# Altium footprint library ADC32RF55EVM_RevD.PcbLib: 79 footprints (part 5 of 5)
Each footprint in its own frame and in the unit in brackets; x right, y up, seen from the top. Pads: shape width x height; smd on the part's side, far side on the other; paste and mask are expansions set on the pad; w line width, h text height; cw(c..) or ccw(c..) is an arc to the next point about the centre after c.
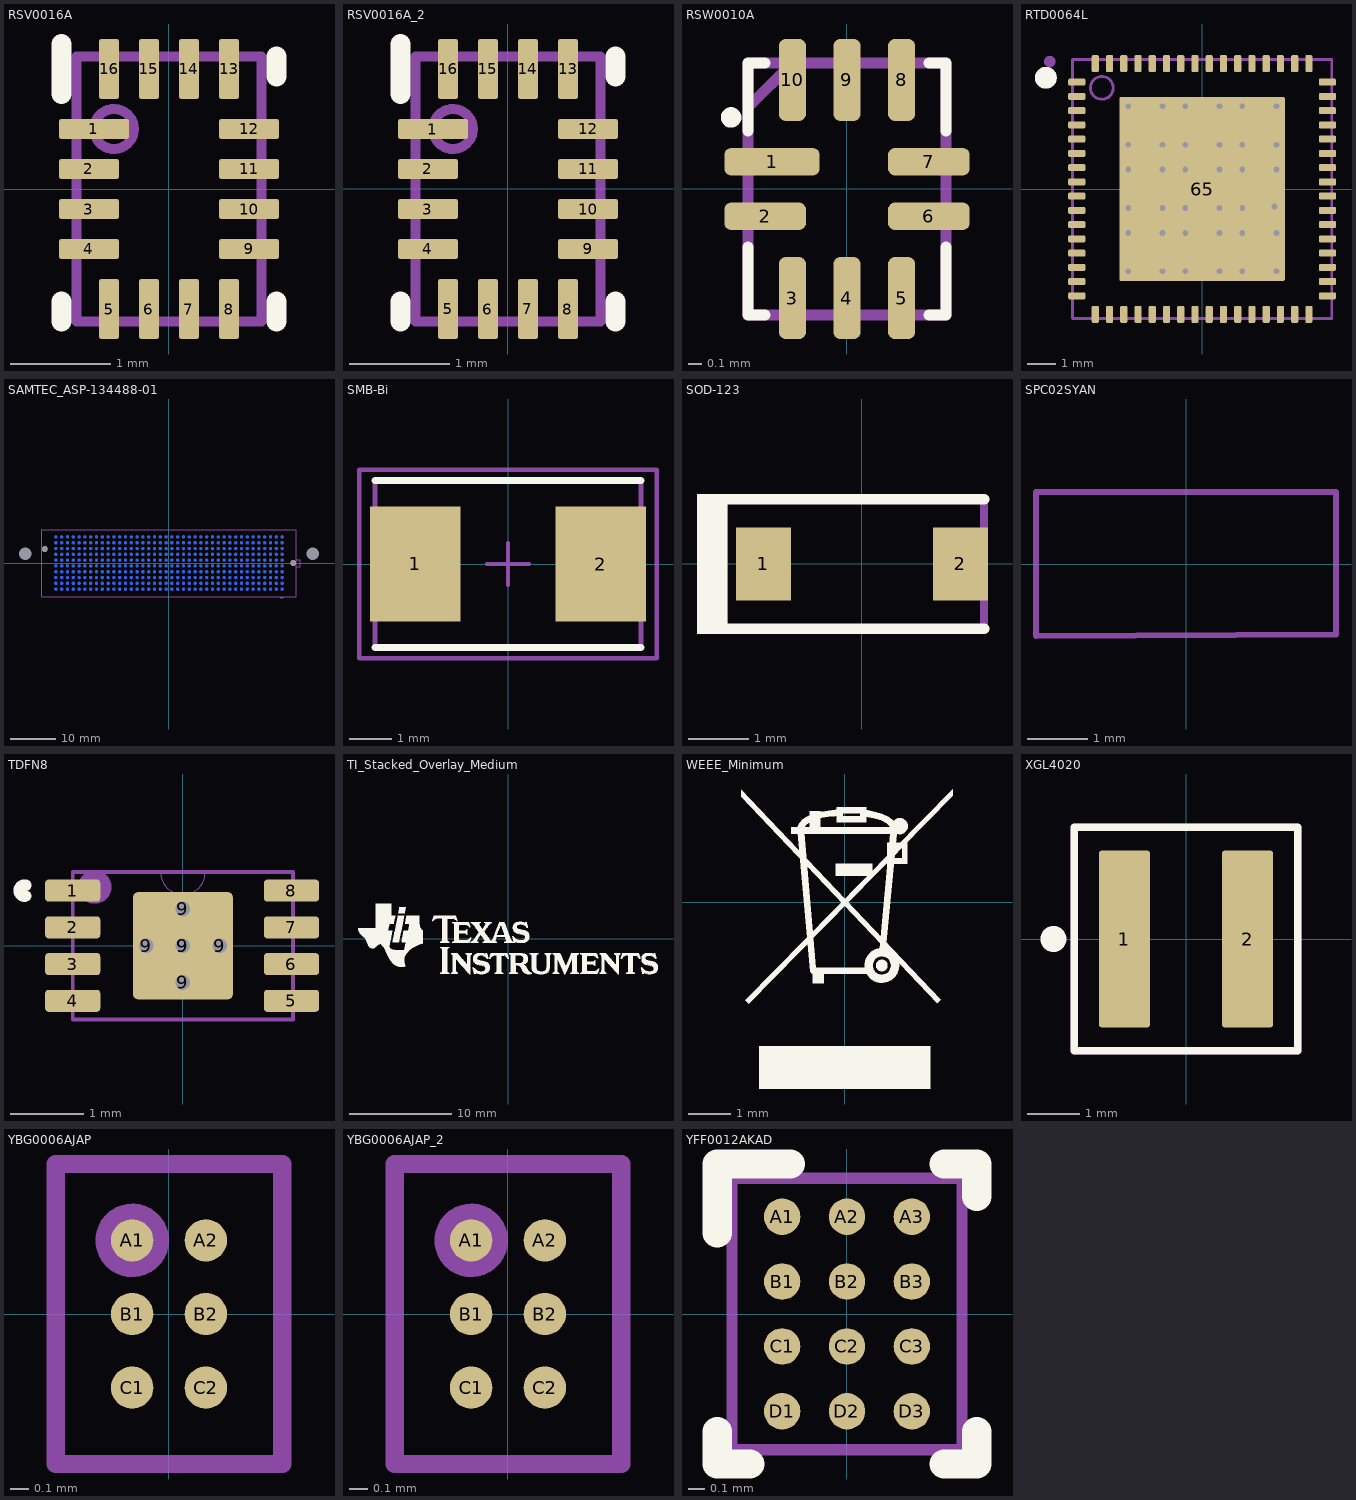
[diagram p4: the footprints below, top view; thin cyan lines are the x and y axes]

## RSV0016A [mm] "QFN, 16-Leads, Body 1.8x2.6mm, Pitch 0.4mm, TI Recommended"
height 0.55
pads (16):
  rrect25% 0.7x0.2 smd mask+0.05: 1(-0.75,0.6)
  rrect25% 0.6x0.2 smd mask+0.05: 2(-0.8,0.2) 3(-0.8,-0.2) 4(-0.8,-0.6) 9(0.8,-0.6) 10(0.8,-0.2) 11(0.8,0.2) 12(0.8,0.6)
  rrect25% 0.2x0.6 smd mask+0.05: 5(-0.6,-1.2) 6(-0.2,-1.2) 7(0.2,-1.2) 8(0.6,-1.2) 13(0.6,1.2) 14(0.2,1.2) 15(-0.2,1.2) 16(-0.6,1.2)
Top Overlay:
  lines w0.2: -1.075,-1.325 -1.075,-1.125 ; -1.075,0.95 -1.075,1.45 ; 1.075,-1.325 1.075,-1.125 ; 1.075,1.125 1.075,1.325
Mechanical 5:
  circle w0.1: c-0.55,0.6 r0.2
  lines w0.1: -0.925,-1.325 -0.925,1.325 0.925,1.325 0.925,-1.325 -0.925,-1.325
  text ".Designator" at -0.254,0 h0.64
3D body "RSV0016A.step": height 0.49, standoff 0, extent -0.855,-1.305 0.855,1.305

## RSV0016A_2 [mm]
pads (16):
  rrect25% 0.7x0.2 smd mask+0.05: 1(-0.75,0.6)
  rrect25% 0.6x0.2 smd mask+0.05: 2(-0.8,0.2) 3(-0.8,-0.2) 4(-0.8,-0.6) 9(0.8,-0.6) 10(0.8,-0.2) 11(0.8,0.2) 12(0.8,0.6)
  rrect25% 0.2x0.6 smd mask+0.05: 5(-0.6,-1.2) 6(-0.2,-1.2) 7(0.2,-1.2) 8(0.6,-1.2) 13(0.6,1.2) 14(0.2,1.2) 15(-0.2,1.2) 16(-0.6,1.2)
Top Overlay:
  lines w0.2: -1.075,-1.325 -1.075,-1.125 ; -1.075,0.95 -1.075,1.45 ; 1.075,-1.325 1.075,-1.125 ; 1.075,1.125 1.075,1.325
Mechanical 5:
  circle w0.1: c-0.55,0.6 r0.2
  lines w0.1: -0.925,-1.325 -0.925,1.325 0.925,1.325 0.925,-1.325 -0.925,-1.325
  text ".Designator" at -0.254,0 h0.64
3D body: height 0.56, standoff 0.4, extent -0.749,0.401 -0.351,0.799
3D body: height 0.55, standoff 0, extent -0.925,-1.325 0.925,1.325

## RSW0010A [mm]
height 4.27
pads (10):
  rrect50% 0.7x0.2 smd mask+0.05: 1(-0.55,0.2)
  rrect50% 0.6x0.2 smd mask+0.05: 2(-0.6,-0.2) 6(0.6,-0.2) 7(0.6,0.2)
  rrect50% 0.2x0.6 smd mask+0.05: 3(-0.4,-0.8) 4(0,-0.8) 5(0.4,-0.8) 8(0.4,0.8) 9(0,0.8) 10(-0.4,0.8)
Top Overlay:
  circle w0.1: c-0.85,0.525 r0.025
  lines w0.08: -0.725,-0.425 -0.725,-0.925 -0.6,-0.925 ; -0.725,0.425 -0.725,0.925 -0.6,0.925 ; 0.6,-0.925 0.725,-0.925 0.725,-0.425 ; 0.6,0.925 0.725,0.925 0.725,0.425
Mechanical 5:
  lines w0.08: -0.725,0.525 -0.725,0.55 -0.725,0.6 -0.4,0.925 ; -0.725,-0.925 -0.725,0.925 ; -0.725,-0.925 -0.725,0.925 ; -0.725,-0.925 0.725,-0.925 ; -0.725,-0.925 0.725,-0.925 ; -0.725,0.925 0.725,0.925 ; -0.725,0.925 0.725,0.925 ; 0.725,-0.925 0.725,0.925 ; 0.725,-0.925 0.725,0.925
  text ".Designator" at -0.254,0 h0.64
3D body "RSW0010A.stp": height 0.55, standoff 0, extent -0.7,-0.9 0.7,0.9

## RTD0064L [mm] "VQFN-64"
height 0.9
pads (65):
  rrect40% 0.6x0.25 smd: 1(-4.4,3.75) 2(-4.4,3.25) 3(-4.4,2.75) 4(-4.4,2.25) 5(-4.4,1.75) 6(-4.4,1.25) 7(-4.4,0.75) 8(-4.4,0.25) 9(-4.4,-0.25) 10(-4.4,-0.75) 11(-4.4,-1.25) 12(-4.4,-1.75) 13(-4.4,-2.25) 14(-4.4,-2.75) 15(-4.4,-3.25) 16(-4.4,-3.75) 33(4.4,-3.75) 34(4.4,-3.25) 35(4.4,-2.75) 36(4.4,-2.25) 37(4.4,-1.75) 38(4.4,-1.25) 39(4.4,-0.75) 40(4.4,-0.25) 41(4.4,0.25) 42(4.4,0.75) 43(4.4,1.25) 44(4.4,1.75) 45(4.4,2.25) 46(4.4,2.75) 47(4.4,3.25) 48(4.4,3.75)
  rrect40% 0.25x0.6 smd: 17(-3.75,-4.4) 18(-3.25,-4.4) 19(-2.75,-4.4) 20(-2.25,-4.4) 21(-1.75,-4.4) 22(-1.25,-4.4) 23(-0.75,-4.4) 24(-0.25,-4.4) 25(0.25,-4.4) 26(0.75,-4.4) 27(1.25,-4.4) 28(1.75,-4.4) 29(2.25,-4.4) 30(2.75,-4.4) 31(3.25,-4.4) 32(3.75,-4.4) 49(3.75,4.4) 50(3.25,4.4) 51(2.75,4.4) 52(2.25,4.4) 53(1.75,4.4) 54(1.25,4.4) 55(0.75,4.4) 56(0.25,4.4) 57(-0.25,4.4) 58(-0.75,4.4) 59(-1.25,4.4) 60(-1.75,4.4) 61(-2.25,4.4) 62(-2.75,4.4) 63(-3.25,4.4) 64(-3.75,4.4)
  rrect2% 5.808x6.466 smd paste-3.5: 65(0,0)
via 0.609,-2.889 diameter 0.457 hole 0.203
via -1.393,-2.889 diameter 0.457 hole 0.203
via 0.609,-0.667 diameter 0.457 hole 0.203
via -2.595,-1.541 diameter 0.457 hole 0.203
via -2.595,-2.889 diameter 0.457 hole 0.203
via -1.393,-1.541 diameter 0.457 hole 0.203
via -0.593,-1.541 diameter 0.457 hole 0.203
via 0.609,-1.541 diameter 0.457 hole 0.203
via 1.41,-1.541 diameter 0.457 hole 0.203
via 1.41,-2.889 diameter 0.457 hole 0.203
via 2.612,-2.889 diameter 0.457 hole 0.203
via 2.612,-1.541 diameter 0.457 hole 0.203
via -0.593,-2.889 diameter 0.457 hole 0.203
via 0.609,0.681 diameter 0.457 hole 0.203
via -2.595,0.681 diameter 0.457 hole 0.203
via -0.593,-0.667 diameter 0.457 hole 0.203
via -1.393,-0.667 diameter 0.457 hole 0.203
via -2.595,-0.667 diameter 0.457 hole 0.203
via -0.593,0.681 diameter 0.457 hole 0.203
via -1.393,0.681 diameter 0.457 hole 0.203
via 1.41,-0.667 diameter 0.457 hole 0.203
via 1.41,1.555 diameter 0.457 hole 0.203
via 1.41,0.681 diameter 0.457 hole 0.203
via 2.612,1.555 diameter 0.457 hole 0.203
via 2.612,0.681 diameter 0.457 hole 0.203
via 2.54,-0.61 diameter 0.457 hole 0.203
via -2.595,2.903 diameter 0.457 hole 0.203
via -1.393,2.903 diameter 0.457 hole 0.203
via 2.612,2.903 diameter 0.457 hole 0.203
via 0.609,1.555 diameter 0.457 hole 0.203
via 0.609,2.903 diameter 0.457 hole 0.203
via -0.593,1.555 diameter 0.457 hole 0.203
via -0.593,2.903 diameter 0.457 hole 0.203
via -1.393,1.555 diameter 0.457 hole 0.203
via -2.595,1.555 diameter 0.457 hole 0.203
via 1.41,2.903 diameter 0.457 hole 0.203
Top Overlay:
  circle w0.2: c-5.482,3.903 r0.284
  region: -5.831,3.903 -5.502,4.231 -5.127,3.857 -5.456,3.528
Top Paste:
  drawing of 9 lines, arcs and shapes, not listed
Mechanical 5:
  circle w0.1: c-3.52,3.55 r0.4
  lines w0.1: -3.145,4.55 -2.895,4.55 -2.645,4.55 ; -4.55,-4.55 4.55,-4.55 4.55,4.55 -4.55,4.55 -4.55,-4.55
  text ".Designator" at 0,0 h0.51
Mechanical 13:
  circle w0.2: c-5.346,4.473 r0.1
3D body: height 0.9, standoff 0, extent -3.919,3.151 -3.121,3.949
3D body "RTD0064L.stp": height 0.85, standoff 0, extent -4.5,-4.5 4.5,4.5

## SAMTEC_ASP-134488-01 [mm]
pads (404):
  round 0.64 smd far side paste+0.125: A1(24.79,-5.715) A2(23.52,-5.715) A3(22.25,-5.715) A4(20.98,-5.715) A5(19.71,-5.715) A6(18.44,-5.715) A7(17.17,-5.715) A8(15.9,-5.715) A9(14.63,-5.715) A10(13.36,-5.715) A11(12.09,-5.715) A12(10.82,-5.715) A13(9.55,-5.715) A14(8.28,-5.715) A15(7.01,-5.715) A16(5.74,-5.715) A17(4.47,-5.715) A18(3.2,-5.715) A19(1.93,-5.715) A20(0.66,-5.715) A21(-0.61,-5.715) A22(-1.88,-5.715) A23(-3.15,-5.715) A24(-4.42,-5.715) A25(-5.69,-5.715) A26(-6.96,-5.715) A27(-8.23,-5.715) A28(-9.5,-5.715) A29(-10.77,-5.715) A30(-12.04,-5.715) A31(-13.31,-5.715) A32(-14.58,-5.715) A33(-15.85,-5.715) A34(-17.12,-5.715) A35(-18.39,-5.715) A36(-19.66,-5.715) A37(-20.93,-5.715) A38(-22.2,-5.715) A39(-23.47,-5.715) A40(-24.74,-5.715) B1(24.79,-4.445) B2(23.52,-4.445) B3(22.25,-4.445) B4(20.98,-4.445) B5(19.71,-4.445) B6(18.44,-4.445) B7(17.17,-4.445) B8(15.9,-4.445) B9(14.63,-4.445) B10(13.36,-4.445) B11(12.09,-4.445) B12(10.82,-4.445) B13(9.55,-4.445) B14(8.28,-4.445) B15(7.01,-4.445) B16(5.74,-4.445) B17(4.47,-4.445) B18(3.2,-4.445) B19(1.93,-4.445) B20(0.66,-4.445) B21(-0.61,-4.445) B22(-1.88,-4.445) B23(-3.15,-4.445) B24(-4.42,-4.445) B25(-5.69,-4.445) B26(-6.96,-4.445) B27(-8.23,-4.445) B28(-9.5,-4.445) B29(-10.77,-4.445) B30(-12.04,-4.445) B31(-13.31,-4.445) B32(-14.58,-4.445) B33(-15.85,-4.445) B34(-17.12,-4.445) B35(-18.39,-4.445) B36(-19.66,-4.445) B37(-20.93,-4.445) B38(-22.2,-4.445) B39(-23.47,-4.445) B40(-24.74,-4.445) C1(24.79,-3.175) C2(23.52,-3.175) C3(22.25,-3.175) C4(20.98,-3.175) C5(19.71,-3.175) C6(18.44,-3.175) C7(17.17,-3.175) C8(15.9,-3.175) C9(14.63,-3.175) C10(13.36,-3.175) C11(12.09,-3.175) C12(10.82,-3.175) C13(9.55,-3.175) C14(8.28,-3.175) C15(7.01,-3.175) C16(5.74,-3.175) C17(4.47,-3.175) C18(3.2,-3.175) C19(1.93,-3.175) C20(0.66,-3.175) C21(-0.61,-3.175) C22(-1.88,-3.175) C23(-3.15,-3.175) C24(-4.42,-3.175) C25(-5.69,-3.175) C26(-6.96,-3.175) C27(-8.23,-3.175) C28(-9.5,-3.175) C29(-10.77,-3.175) C30(-12.04,-3.175) C31(-13.31,-3.175) C32(-14.58,-3.175) C33(-15.85,-3.175) C34(-17.12,-3.175) C35(-18.39,-3.175) C36(-19.66,-3.175) C37(-20.93,-3.175) C38(-22.2,-3.175) C39(-23.47,-3.175) C40(-24.74,-3.175) D1(24.79,-1.905) D2(23.52,-1.905) D3(22.25,-1.905) D4(20.98,-1.905) D5(19.71,-1.905) D6(18.44,-1.905) D7(17.17,-1.905) D8(15.9,-1.905) D9(14.63,-1.905) D10(13.36,-1.905) D11(12.09,-1.905) D12(10.82,-1.905) D13(9.55,-1.905) D14(8.28,-1.905) D15(7.01,-1.905) D16(5.74,-1.905) D17(4.47,-1.905) D18(3.2,-1.905) D19(1.93,-1.905) D20(0.66,-1.905) D21(-0.61,-1.905) D22(-1.88,-1.905) D23(-3.15,-1.905) D24(-4.42,-1.905) D25(-5.69,-1.905) D26(-6.96,-1.905) D27(-8.23,-1.905) D28(-9.5,-1.905) D29(-10.77,-1.905) D30(-12.04,-1.905) D31(-13.31,-1.905) D32(-14.58,-1.905) D33(-15.85,-1.905) D34(-17.12,-1.905) D35(-18.39,-1.905) D36(-19.66,-1.905) D37(-20.93,-1.905) D38(-22.2,-1.905) D39(-23.47,-1.905) D40(-24.74,-1.905) E1(24.79,-0.635) E2(23.52,-0.635) E3(22.25,-0.635) E4(20.98,-0.635) E5(19.71,-0.635) E6(18.44,-0.635) E7(17.17,-0.635) E8(15.9,-0.635) E9(14.63,-0.635) E10(13.36,-0.635) E11(12.09,-0.635) E12(10.82,-0.635) E13(9.55,-0.635) E14(8.28,-0.635) E15(7.01,-0.635) E16(5.74,-0.635) E17(4.47,-0.635) E18(3.2,-0.635) E19(1.93,-0.635) E20(0.66,-0.635) E21(-0.61,-0.635) E22(-1.88,-0.635) E23(-3.15,-0.635) E24(-4.42,-0.635) E25(-5.69,-0.635) E26(-6.96,-0.635) E27(-8.23,-0.635) E28(-9.5,-0.635) E29(-10.77,-0.635) E30(-12.04,-0.635) E31(-13.31,-0.635) E32(-14.58,-0.635) E33(-15.85,-0.635) E34(-17.12,-0.635) E35(-18.39,-0.635) E36(-19.66,-0.635) E37(-20.93,-0.635) E38(-22.2,-0.635) E39(-23.47,-0.635) E40(-24.74,-0.635) F1(24.79,0.635) F2(23.52,0.635) F3(22.25,0.635) F4(20.98,0.635) F5(19.71,0.635) F6(18.44,0.635) F7(17.17,0.635) F8(15.9,0.635) F9(14.63,0.635) F10(13.36,0.635) F11(12.09,0.635) F12(10.82,0.635) F13(9.55,0.635) F14(8.28,0.635) F15(7.01,0.635) F16(5.74,0.635) F17(4.47,0.635) F18(3.2,0.635) F19(1.93,0.635) F20(0.66,0.635) F21(-0.61,0.635) F22(-1.88,0.635) F23(-3.15,0.635) F24(-4.42,0.635) F25(-5.69,0.635) F26(-6.96,0.635) F27(-8.23,0.635) F28(-9.5,0.635) F29(-10.77,0.635) F30(-12.04,0.635) F31(-13.31,0.635) F32(-14.58,0.635) F33(-15.85,0.635) F34(-17.12,0.635) F35(-18.39,0.635) F36(-19.66,0.635) F37(-20.93,0.635) F38(-22.2,0.635) F39(-23.47,0.635) F40(-24.74,0.635) G1(24.79,1.905) G2(23.52,1.905) G3(22.25,1.905) G4(20.98,1.905) G5(19.71,1.905) G6(18.44,1.905) G7(17.17,1.905) G8(15.9,1.905) G9(14.63,1.905) G10(13.36,1.905) G11(12.09,1.905) G12(10.82,1.905) G13(9.55,1.905) G14(8.28,1.905) G15(7.01,1.905) G16(5.74,1.905) G17(4.47,1.905) G18(3.2,1.905) G19(1.93,1.905) G20(0.66,1.905) G21(-0.61,1.905) G22(-1.88,1.905) G23(-3.15,1.905) G24(-4.42,1.905) G25(-5.69,1.905) G26(-6.96,1.905) G27(-8.23,1.905) G28(-9.5,1.905) G29(-10.77,1.905) G30(-12.04,1.905) G31(-13.31,1.905) G32(-14.58,1.905) G33(-15.85,1.905) G34(-17.12,1.905) G35(-18.39,1.905) G36(-19.66,1.905) G37(-20.93,1.905) G38(-22.2,1.905) G39(-23.47,1.905) G40(-24.74,1.905) H1(24.79,3.175) H2(23.52,3.175) H3(22.25,3.175) H4(20.98,3.175) H5(19.71,3.175) H6(18.44,3.175) H7(17.17,3.175) H8(15.9,3.175) H9(14.63,3.175) H10(13.36,3.175) H11(12.09,3.175) H12(10.82,3.175) H13(9.55,3.175) H14(8.28,3.175) H15(7.01,3.175) H16(5.74,3.175) H17(4.47,3.175) H18(3.2,3.175) H19(1.93,3.175) H20(0.66,3.175) H21(-0.61,3.175) H22(-1.88,3.175) H23(-3.15,3.175) H24(-4.42,3.175) H25(-5.69,3.175) H26(-6.96,3.175) H27(-8.23,3.175) H28(-9.5,3.175) H29(-10.77,3.175) H30(-12.04,3.175) H31(-13.31,3.175) H32(-14.58,3.175) H33(-15.85,3.175) H34(-17.12,3.175) H35(-18.39,3.175) H36(-19.66,3.175) H37(-20.93,3.175) H38(-22.2,3.175) H39(-23.47,3.175) H40(-24.74,3.175) J1(24.79,4.445) J2(23.52,4.445) J3(22.25,4.445) J4(20.98,4.445) J5(19.71,4.445) J6(18.44,4.445) J7(17.17,4.445) J8(15.9,4.445) J9(14.63,4.445) J10(13.36,4.445) J11(12.09,4.445) J12(10.82,4.445) J13(9.55,4.445) J14(8.28,4.445) J15(7.01,4.445) J16(5.74,4.445) J17(4.47,4.445) J18(3.2,4.445) J19(1.93,4.445) J20(0.66,4.445) J21(-0.61,4.445) J22(-1.88,4.445) J23(-3.15,4.445) J24(-4.42,4.445) J25(-5.69,4.445) J26(-6.96,4.445) J27(-8.23,4.445) J28(-9.5,4.445) J29(-10.77,4.445) J30(-12.04,4.445) J31(-13.31,4.445) J32(-14.58,4.445) J33(-15.85,4.445) J34(-17.12,4.445) J35(-18.39,4.445) J36(-19.66,4.445) J37(-20.93,4.445) J38(-22.2,4.445) J39(-23.47,4.445) J40(-24.74,4.445) K1(24.79,5.715) K2(23.52,5.715) K3(22.25,5.715) K4(20.98,5.715) K5(19.71,5.715) K6(18.44,5.715) K7(17.17,5.715) K8(15.9,5.715) K9(14.63,5.715) K10(13.36,5.715) K11(12.09,5.715) K12(10.82,5.715) K13(9.55,5.715) K14(8.28,5.715) K15(7.01,5.715) K16(5.74,5.715) K17(4.47,5.715) K18(3.2,5.715) K19(1.93,5.715) K20(0.66,5.715) K21(-0.61,5.715) K22(-1.88,5.715) K23(-3.15,5.715) K24(-4.42,5.715) K25(-5.69,5.715) K26(-6.96,5.715) K27(-8.23,5.715) K28(-9.5,5.715) K29(-10.77,5.715) K30(-12.04,5.715) K31(-13.31,5.715) K32(-14.58,5.715) K33(-15.85,5.715) K34(-17.12,5.715) K35(-18.39,5.715) K36(-19.66,5.715) K37(-20.93,5.715) K38(-22.2,5.715) K39(-23.47,5.715) K40(-24.74,5.715)
  round 0 hole 2.69 unplated: ""(-31.471,2.007) ""(31.521,2.007)
  round 1.27 hole 1.27 unplated: ""(-27.166,3.05) ""(27.216,0)
Bottom Overlay:
  region: 25.139,-7.442 24.339,-7.442 24.339,-7.76 25.139,-7.76
  lines w0.2: -27.865,1.905 -27.865,-7.34 27.915,-7.34 27.915,-0.76 28.805,-0.76 28.805,0.76 27.915,0.76 27.915,7.34 -27.865,7.34 -27.865,4.245
Mechanical 5:
  text ".Designator" at -0.102,-0.339 h0.64
Mechanical 6:
  region: 25.126,-7.442 24.326,-7.442 24.326,-7.76 25.126,-7.76
Mechanical 13:
  lines w0.2: 27.915,-0.76 27.915,-7.34 -27.865,-7.34 -27.865,7.34 27.915,7.34 27.915,0.76 ; 27.915,-0.76 27.915,0.76 ; 27.915,-0.76 28.805,-0.76 28.805,0.76 27.915,0.76
3D body "ASP-134488-01.stp": height 7.11, standoff -1.27, extent -27.864,-7.34 28.806,7.34

## SMB-Bi [mm] "Molded Diode, 2-Leads, Body 5.4x3.6mm, IPC Medium Density, based on OnSemi component dimensions"
height 2.65
pads (2):
  rect 2.159x2.743 smd: 1(-2.21,0) 2(2.21,0)
Top Overlay:
  lines w0.178: -3.175,-1.994 3.175,-1.994 ; -3.175,1.994 3.175,1.994
Mechanical 5:
  lines w0.127: -3.175,-1.994 -3.175,-1.765 -3.175,1.765 -3.175,1.994 3.175,1.994 3.175,1.765 3.175,-1.765 3.175,-1.994 -3.175,-1.994
  text ".Designator" at -2.311,-0.508 h1.02
Mechanical 15:
  lines w0.1: -0.5,0 0.5,0 ; 0,-0.5 0,0.5 ; -3.55,-2.25 3.55,-2.25 3.55,2.25 -3.55,2.25 -3.55,-2.25
3D body "SMB-Bi.stp": height 2.26, standoff 0.01, extent -2.65,-1.85 2.65,1.85

## SOD-123 [mm] "On Semi recommended land pattern"
height 1.35
pads (2):
  rect 0.915x1.22 smd: 1(-1.637,0) 2(1.637,0)
Top Overlay:
  rectangle: -2.743,-1.168 -2.235,1.168
  lines w0.178: -2.413,-1.079 2.032,-1.079 ; -2.413,1.079 2.032,1.079
Mechanical 5:
  rectangle: -2.743,-1.168 -2.235,1.168
  lines w0.127: -2.413,-1.079 2.032,-1.079 2.032,1.079 -2.413,1.079
  text ".Designator" at -1.956,-0.33 h0.76
3D body "SOD-123.stp": height 1.35, standoff 0, extent -1.932,-0.9 1.932,0.9

## SPC02SYAN [mil] "SULLINS"
height 256
pads (1):
  round 1 on Mech3: 0(0,0)
Mechanical 5:
  lines w4: -98.43,-47.24 98.43,-46.26 98.43,47.24 -98.43,47.24 -98.43,-47.24
3D body "Sullins_SPC02SYAN.stp": height 366, standoff 110, extent -98.49,-46.99 98.51,47

## TDFN8 [mm]
height 4.27
pads (14):
  rrect30% 0.75x0.3 smd paste+0 mask+0.05: 1(-1.5,0.75) 2(-1.5,0.25) 3(-1.5,-0.25) 4(-1.5,-0.75) 5(1.478,-0.75) 6(1.478,-0.25) 7(1.478,0.25) 8(1.478,0.75)
  round 0.327 / inner round 0.454 / far side round 0.454 hole 0.2 mask+0.05: 9(-0.5,0) 9(0,-0.5) 9(0,0) 9(0,0.5) 9(0.5,0)
  rrect10% 1.36x1.46 smd paste+0 mask+0.05: 9(0,0)
Top Overlay:
  lines w0.152: -2.136,0.676 cw(c-2.155,0.75) -2.136,0.824
Mechanical 5:
  circle w0.254: c-1.2,0.8 r0.1
  lines w0.051: -1.499,-1.003 -1.499,1.003 1.499,1.003 1.499,-1.003 -1.499,-1.003
  text ".Designator" at -0.127,0.339 h0.64
Mechanical 13:
  lines w0: -0.305,1.003 ccw(c0,1.003) 0.305,1.003
  lines w0.025: -1.499,-1.003 -1.499,1.003 1.499,1.003 1.499,-1.003 -1.499,-1.003
3D body "TDFN8_2x3MC_MCH.step": height 0.76, standoff 0, extent -1.499,-1.003 1.499,1.003

## TI_Stacked_Overlay_Medium [mm]
Top Overlay:
  drawing of 18 lines, arcs and shapes, not listed

## WEEE_Minimum [mm] "WEEElie bin"
height 1
Top Overlay:
  drawing of 23 lines, arcs and shapes, not listed

## XGL4020 [mm]
height 4.27
pads (2):
  rrect10% 0.98x3.4 smd paste+0 mask+0: 1(-1.185,0) 2(1.185,0)
Top Overlay:
  circle w0.25: c-2.55,0 r0.125
  lines w0.15: -2.15,-2.15 -2.15,2.15 2.15,2.15 2.15,-2.15 -2.15,-2.15
Mechanical 5:
  lines w0.15: -2.15,-2.15 -2.15,2.15 2.15,2.15 2.15,-2.15 -2.15,-2.15
  text ".Designator" at -0.127,0.339 h0.64
3D body "Ind_XGL4020-111MEC_SMT_4MM0_4MM0.STEP": height 0.25, standoff 0, extent -2.25,-2.25 2.25,2.25

## YBG0006AJAP [mm] "DSBGA-6"
height 0.5
pads (6):
  round 0.23 smd paste-0.23 mask+0.032: A1(-0.2,0.4) A2(0.2,0.4) B1(-0.2,0) B2(0.2,0) C1(-0.2,-0.4) C2(0.2,-0.4)
Top Paste:
  drawing of 6 lines, arcs and shapes, not listed
Mechanical 5:
  circle w0.1: c-0.2,0.4 r0.15
  lines w0.1: -0.615,-0.815 -0.615,0.815 0.615,0.815 0.615,-0.815 -0.615,-0.815
  text ".Designator" at -0.4,-0.1 h0.25
3D body "YBG0006.step": height 0.33, standoff -0.13, extent -0.34,-0.54 0.34,0.54

## YBG0006AJAP_2 [mm]
pads (6):
  round 0.23 smd paste-0.23 mask+0.032: A1(-0.2,0.4) A2(0.2,0.4) B1(-0.2,0) B2(0.2,0) C1(-0.2,-0.4) C2(0.2,-0.4)
Top Paste:
  drawing of 6 lines, arcs and shapes, not listed
Mechanical 5:
  circle w0.1: c-0.2,0.4 r0.15
  lines w0.1: -0.615,-0.815 0.615,-0.815 0.615,0.815 -0.615,0.815 -0.615,-0.815
  text ".Designator" at -0.4,-0.1 h0.25
3D body "YBG0006AJAP.step": height 0.5, standoff 0, extent -0.615,-0.815 0.615,0.815

## YFF0012AKAD [mm] "TI DSBGA 1.675x1.418mm"
height 0.625
pads (12):
  round 0.225 smd paste-0.13 mask+0: A1(-0.4,0.6) A2(0,0.6) A3(0.4,0.6) B1(-0.4,0.2) B2(0,0.2) B3(0.4,0.2) C1(-0.4,-0.2) C2(0,-0.2) C3(0.4,-0.2) D1(-0.4,-0.6) D2(0,-0.6) D3(0.4,-0.6)
Top Overlay:
  lines w0.18: -0.8,-0.725 -0.8,-0.925 -0.6,-0.925 ; -0.8,0.5 -0.8,0.925 -0.35,0.925 ; 0.6,-0.925 0.8,-0.925 0.8,-0.725 ; 0.6,0.925 0.8,0.925 0.8,0.725
Top Paste:
  circle w0.05: c0.475,0.525 r0.025
  circle w0.05: c0.325,0.675 r0.025
  circle w0.05: c0.475,0.675 r0.025
  circle w0.05: c0.325,0.525 r0.025
  circle w0.05: c0.325,0.125 r0.025
  circle w0.05: c0.475,0.275 r0.025
  circle w0.05: c0.325,0.275 r0.025
  circle w0.05: c0.475,0.125 r0.025
  circle w0.05: c0.325,-0.275 r0.025
  circle w0.05: c0.475,-0.125 r0.025
  circle w0.05: c0.325,-0.125 r0.025
  circle w0.05: c0.475,-0.275 r0.025
  circle w0.05: c0.325,-0.675 r0.025
  circle w0.05: c0.475,-0.525 r0.025
  circle w0.05: c0.325,-0.525 r0.025
  circle w0.05: c0.475,-0.675 r0.025
  circle w0.05: c0.075,0.525 r0.025
  circle w0.05: c-0.075,0.675 r0.025
  circle w0.05: c0.075,0.675 r0.025
  circle w0.05: c-0.075,0.525 r0.025
  circle w0.05: c-0.075,0.125 r0.025
  circle w0.05: c0.075,0.275 r0.025
  circle w0.05: c-0.075,0.275 r0.025
  circle w0.05: c0.075,0.125 r0.025
  circle w0.05: c-0.075,-0.275 r0.025
  circle w0.05: c0.075,-0.125 r0.025
  circle w0.05: c-0.075,-0.125 r0.025
  circle w0.05: c0.075,-0.275 r0.025
  circle w0.05: c-0.075,-0.675 r0.025
  circle w0.05: c0.075,-0.525 r0.025
  circle w0.05: c-0.075,-0.525 r0.025
  circle w0.05: c0.075,-0.675 r0.025
  circle w0.05: c-0.325,0.525 r0.025
  circle w0.05: c-0.475,0.675 r0.025
  circle w0.05: c-0.325,0.675 r0.025
  circle w0.05: c-0.475,0.525 r0.025
  circle w0.05: c-0.475,0.125 r0.025
  circle w0.05: c-0.325,0.275 r0.025
  circle w0.05: c-0.475,0.275 r0.025
  circle w0.05: c-0.325,0.125 r0.025
  circle w0.05: c-0.475,-0.275 r0.025
  circle w0.05: c-0.325,-0.125 r0.025
  circle w0.05: c-0.475,-0.125 r0.025
  circle w0.05: c-0.325,-0.275 r0.025
  circle w0.05: c-0.475,-0.675 r0.025
  circle w0.05: c-0.325,-0.525 r0.025
  circle w0.05: c-0.475,-0.525 r0.025
  circle w0.05: c-0.325,-0.675 r0.025
  region: 0.275,0.675 0.275,0.525 0.325,0.525 0.325,0.675
  region: 0.475,0.725 0.325,0.725 0.325,0.675 0.475,0.675
  region: 0.525,0.525 0.525,0.675 0.475,0.675 0.475,0.525
  rectangle: 0.325,0.475 0.475,0.525
  region: 0.475,0.675 0.325,0.675 0.325,0.525 0.475,0.525
  region: 0.475,0.275 0.325,0.275 0.325,0.125 0.475,0.125
  rectangle: 0.325,0.075 0.475,0.125
  region: 0.525,0.125 0.525,0.275 0.475,0.275 0.475,0.125
  region: 0.475,0.325 0.325,0.325 0.325,0.275 0.475,0.275
  region: 0.275,0.275 0.275,0.125 0.325,0.125 0.325,0.275
  region: 0.475,-0.125 0.325,-0.125 0.325,-0.275 0.475,-0.275
  rectangle: 0.325,-0.325 0.475,-0.275
  region: 0.525,-0.275 0.525,-0.125 0.475,-0.125 0.475,-0.275
  region: 0.475,-0.075 0.325,-0.075 0.325,-0.125 0.475,-0.125
  region: 0.275,-0.125 0.275,-0.275 0.325,-0.275 0.325,-0.125
  region: 0.475,-0.525 0.325,-0.525 0.325,-0.675 0.475,-0.675
  rectangle: 0.325,-0.725 0.475,-0.675
  region: 0.525,-0.675 0.525,-0.525 0.475,-0.525 0.475,-0.675
  region: 0.475,-0.475 0.325,-0.475 0.325,-0.525 0.475,-0.525
  region: 0.275,-0.525 0.275,-0.675 0.325,-0.675 0.325,-0.525
  region: -0.125,0.675 -0.125,0.525 -0.075,0.525 -0.075,0.675
  region: 0.075,0.725 -0.075,0.725 -0.075,0.675 0.075,0.675
  region: 0.125,0.525 0.125,0.675 0.075,0.675 0.075,0.525
  rectangle: -0.075,0.475 0.075,0.525
  region: 0.075,0.675 -0.075,0.675 -0.075,0.525 0.075,0.525
  region: 0.075,0.275 -0.075,0.275 -0.075,0.125 0.075,0.125
  rectangle: -0.075,0.075 0.075,0.125
  region: 0.125,0.125 0.125,0.275 0.075,0.275 0.075,0.125
  region: 0.075,0.325 -0.075,0.325 -0.075,0.275 0.075,0.275
  region: -0.125,0.275 -0.125,0.125 -0.075,0.125 -0.075,0.275
  region: 0.075,-0.125 -0.075,-0.125 -0.075,-0.275 0.075,-0.275
  rectangle: -0.075,-0.325 0.075,-0.275
  region: 0.125,-0.275 0.125,-0.125 0.075,-0.125 0.075,-0.275
  region: 0.075,-0.075 -0.075,-0.075 -0.075,-0.125 0.075,-0.125
  region: -0.125,-0.125 -0.125,-0.275 -0.075,-0.275 -0.075,-0.125
  region: 0.075,-0.525 -0.075,-0.525 -0.075,-0.675 0.075,-0.675
  rectangle: -0.075,-0.725 0.075,-0.675
  region: 0.125,-0.675 0.125,-0.525 0.075,-0.525 0.075,-0.675
  region: 0.075,-0.475 -0.075,-0.475 -0.075,-0.525 0.075,-0.525
  region: -0.125,-0.525 -0.125,-0.675 -0.075,-0.675 -0.075,-0.525
  region: -0.525,0.675 -0.525,0.525 -0.475,0.525 -0.475,0.675
  region: -0.325,0.725 -0.475,0.725 -0.475,0.675 -0.325,0.675
  region: -0.275,0.525 -0.275,0.675 -0.325,0.675 -0.325,0.525
  rectangle: -0.475,0.475 -0.325,0.525
  region: -0.325,0.675 -0.475,0.675 -0.475,0.525 -0.325,0.525
  region: -0.325,0.275 -0.475,0.275 -0.475,0.125 -0.325,0.125
  rectangle: -0.475,0.075 -0.325,0.125
  region: -0.275,0.125 -0.275,0.275 -0.325,0.275 -0.325,0.125
  region: -0.325,0.325 -0.475,0.325 -0.475,0.275 -0.325,0.275
  region: -0.525,0.275 -0.525,0.125 -0.475,0.125 -0.475,0.275
  region: -0.325,-0.125 -0.475,-0.125 -0.475,-0.275 -0.325,-0.275
  rectangle: -0.475,-0.325 -0.325,-0.275
  region: -0.275,-0.275 -0.275,-0.125 -0.325,-0.125 -0.325,-0.275
  region: -0.325,-0.075 -0.475,-0.075 -0.475,-0.125 -0.325,-0.125
  region: -0.525,-0.125 -0.525,-0.275 -0.475,-0.275 -0.475,-0.125
  region: -0.325,-0.525 -0.475,-0.525 -0.475,-0.675 -0.325,-0.675
  rectangle: -0.475,-0.725 -0.325,-0.675
  region: -0.275,-0.675 -0.275,-0.525 -0.325,-0.525 -0.325,-0.675
  region: -0.325,-0.475 -0.475,-0.475 -0.475,-0.525 -0.325,-0.525
  region: -0.525,-0.525 -0.525,-0.675 -0.475,-0.675 -0.475,-0.525
Mechanical 5:
  circle w0.06: c-0.4,0.6 r0.08
  lines w0.07: -0.709,-0.837 0.709,-0.837 0.709,0.837 -0.709,0.837 -0.709,-0.837
  text ".Designator" at -0.254,0 h0.64
3D body: height 0.63, standoff 0.6, extent -0.479,0.521 -0.321,0.679
3D body: height 0.63, standoff 0.5, extent -0.479,0.521 -0.321,0.679
3D body: height 0.63, standoff 0, extent -0.708,-0.837 0.708,0.837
